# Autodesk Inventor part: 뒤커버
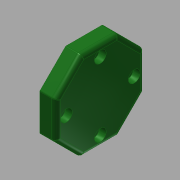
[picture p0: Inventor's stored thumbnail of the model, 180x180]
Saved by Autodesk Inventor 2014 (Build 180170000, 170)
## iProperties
Created: 2015-11
Part Number: 뒤커버
Material: 알루미늄 6061
Document SubType Name: Modeling
Designer: mduedu
Density: 1 g/cm^3
Appearance: 매끄러움 - 짙은 산림 녹색
Author: mduedu
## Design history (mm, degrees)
sketch "스케치5" dims "d66" = 60
  geometry: L1 (12.426, 30)-(30, 12.426); L2 (30, 12.426)-(30, -12.426); L3 (30, -12.426)-(12.426, -30); L4 (12.426, -30)-(-12.426, -30); L5 (-12.426, -30)-(-30, -12.426); L6 (-30, -12.426)-(-30, 12.426); L7 (-30, 12.426)-(-12.426, 30); L8 (-12.426, 30)-(12.426, 30); 4 further points
  constraints: 16 end point, 2 coincident, 2 vertical alignment, 1 midpoint, 19 other
extrude "돌출2" new body sketch "스케치5" distance "d67" = 11; taper "d68" = 0 deg
sketch "스케치6"
  geometry: C1 r 16 at (0, 0); 1 further point
  constraints: 1 centre point, 1 coincident
  dimensions: "d69" = 32 diameter of C1
extrude "돌출3" join sketch "스케치6" distance "d70" = 3; taper "d71" = 0 deg
hole "구멍5" diameter "d74" = 25; stored, may be unused: countersink angle "d78" = 90 deg, drill point angle "d80" = 0 deg; dims "d72" = 10, "d73" = 10, "d75" = 6, "d76" = 4, "d77" = 2, "d79" = 10
fillet "모깎기7" dims "d81" = 1
fillet "모깎기8" dims "d82" = 3
fillet "모깎기9" dims "d83" = 3
fillet "모깎기10" dims "d84" = 0.3
sketch "스케치7" dims "d85" = 46
  geometry: 3 further points
  constraints: 2 vertical alignment, 1 coincident, 2 other
hole "구멍6" sketch "스케치7" at (0, 23) diameter "d86" = 4.5; stored, may be unused: countersink angle "d90" = 90 deg, drill point angle "d92" = 0 deg; dims "d87" = 6, "d88" = 8, "d89" = 4.6, "d91" = 10
node "솔리드2"
pattern_circular "원형 패턴3" dims angle "d94" = 360 deg
